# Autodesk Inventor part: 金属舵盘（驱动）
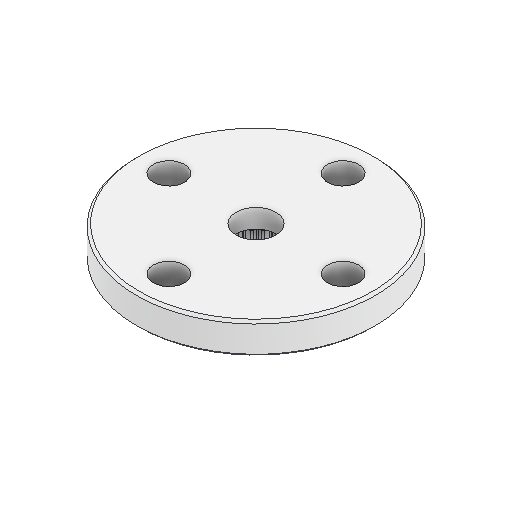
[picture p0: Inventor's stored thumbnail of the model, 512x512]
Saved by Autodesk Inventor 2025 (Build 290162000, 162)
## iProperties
Created: 2025-06
Part Number: 金属舵盘（驱动）
Material: 钢
Document SubType Name: Modeling
Designer: R5800u
Density: 7.85 g/cm^3
Appearance: Default
Author: R5800u
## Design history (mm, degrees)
feature "Body1"
node "Solido1"
